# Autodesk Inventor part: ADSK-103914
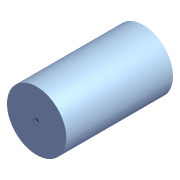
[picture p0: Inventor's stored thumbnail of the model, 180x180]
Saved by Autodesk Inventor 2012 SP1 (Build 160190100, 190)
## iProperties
Shininess: 0.0
Created: 2000-10
Part Number: ADSK-103914
Document SubType Name: Modeling
Stock Number: ADSK-103914
Density: 1 g/cm^3
Material: Default
Density: 0.0
Volumn: 0.0
Area: 0.0
PropertySet Name: Model Information
Control State: 0
Master: False
Checked Out: False
Author: gao
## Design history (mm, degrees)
node "Extrusion1" dims "d2" = 1828.8, "d3" = 0
  sketch "Sketch1"
    geometry: C1 r 38.1 at (0, 0); C2 r 508 at (0, 0)
    constraints: 2 centre point, 1 coincident
    dimensions: "d0" = 76.2 diameter of C1; "d1" = 1016 diameter of C2
workplane "Work Plane1"
body "Solid1"
other parameters: "d4" = -914.4 (= -0.5 x d2)
